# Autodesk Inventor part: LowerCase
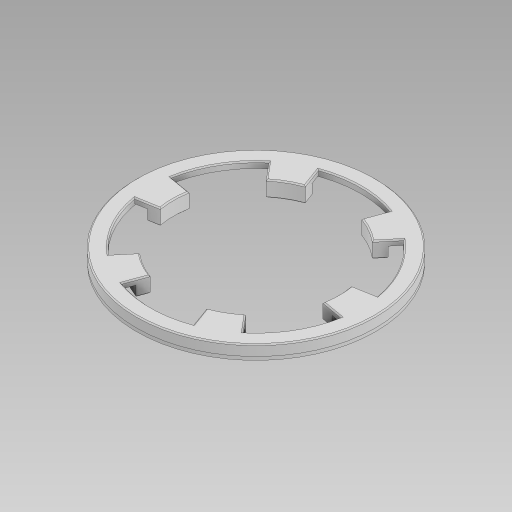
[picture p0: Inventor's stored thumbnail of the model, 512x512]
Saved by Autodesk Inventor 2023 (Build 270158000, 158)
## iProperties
Created: 2024-05
Part Number: LowerCase
Material: 一般
Document SubType Name: Modeling
Designer: kumagai
Density: 1 g/cm^3
Appearance: 既定
Author: kumagai
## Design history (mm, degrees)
derived "CoreSketch.ipt"
  sketch "Vertical"
    geometry: L1 (0, 65.337)-(0, -65.337) reference; L2 (-46.2, 0)-(46.2, 0) reference; L3 (-11, 2)-(11, 2) reference; L4 (11, 2)-(11, -2) reference; L5 (11, -2)-(-11, -2) reference; L6 (-11, -2)-(-11, 2) reference; L7 (11, 2)-(33, 2) reference; L8 (33, 2)-(33, -2) reference; L9 (33, -2)-(11, -2) reference; L10 (11, -2)-(11, 2) reference; L11 (22, 2.772)-(22, -2.683) reference; L12 (-33, 2)-(-11, 2) reference; L13 (-11, 2)-(-11, -2) reference; L14 (-11, -2)-(-33, -2) reference; L15 (-33, -2)-(-33, 2) reference; L16 (-22, 4.087)-(-22, -4.199) reference; L17 (-33, 10)-(-11, 10) reference; L18 (-11, 10)-(-11, 6) reference; L19 (-11, 6)-(-33, 6) reference; L20 (-33, 6)-(-33, 10) reference; L21 (-27.353, 10)-(-16.647, 10) reference; L22 (-16.647, 10)-(-16.647, 16) reference; L23 (-16.647, 16)-(-27.353, 16) reference; L24 (-27.353, 16)-(-27.353, 10) reference; L25 (11, 16)-(33, 16) reference; L26 (33, 16)-(33, 12) reference; L27 (33, 12)-(11, 12) reference; L28 (11, 12)-(11, 16) reference; L29 (16.134, 12)-(27.866, 12) reference; L30 (27.866, 12)-(27.866, 6) reference; L31 (27.866, 6)-(16.134, 6) reference; L32 (16.134, 6)-(16.134, 12) reference; L33 (-22, 18.272)-(-22, 9.031) reference; L34 (22, 22.635)-(22, 12.71) reference; L35 (33, -2)-(35, -2) reference; L36 (35, -2)-(35, 10) reference; L37 (35, 10)-(33, 10) reference; L38 (33, 10)-(33, -2) reference; L39 (0, -4)-(37.5, -4) reference; L40 (40.5, -1)-(40.5, 14) reference; L41 (43.9, -8)-(0, -8) reference; L42 (0, -4)-(0, -8) reference; L43 (35, -2)-(39, -2) reference; L44 (39, -2)-(39, 3.066) reference; L45 (38.45, 8.685)-(41.471, 10.429) reference; L46 (38.45, 10)-(35, 10) reference; L47 (40.5, 9.627)-(41.993, 8.375) reference; L48 (41.55, 3.315)-(40.5, 2.709) reference; L49 (37.5, -4)-(40.5, -1) reference; L50 (-43, 43.294)-(-1, 43.294) reference; L51 (-1, 43.294)-(-1, 26) reference; L52 (-1, 26)-(-43, 26) reference; L53 (-43, 26)-(-43, 43.294) reference; L54 (1, 43.294)-(43, 43.294) reference; L55 (43, 43.294)-(43, 26) reference; L56 (43, 26)-(1, 26) reference; L57 (1, 26)-(1, 43.294) reference; L58 (-22, 45.556)-(-22, 31.232) reference; L59 (22, 47.214)-(22, 32.287) reference; L60 (48, 5.268)-(48, -2.616) reference; L61 (43.6, -11)-(54, -11) reference; L62 (54, -11)-(54, 18) reference; L63 (45.222, -3.461)-(46.5, -2.566) reference; L64 (48, -2.616)-(49.192, -3.808) reference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; A1 r 3.1 centre (40, 6) between (39, 3.066) and (38.45, 8.685) reference; A2 r 3.1 centre (47, -6) between (45.222, -3.461) and (49.192, -3.808) reference; A3 r 3.1 centre (47, 13) between (43.9, 13) and (49, 10.631) reference; 2 further points; 1 other entity
    constraints: 1 other
revolve "回転1" stored, may be unused: angle "d1" = 360 deg
chamfer "面取り1" distance "d2" = 0.5; stored, may be unused: second distance "d3" = 2, angle "d4" = 45 deg
chamfer "面取り2" distance "d5" = 0.1; stored, may be unused: second distance "d6" = 1.5, angle "d7" = 45 deg
sketch "スケッチ4"
  geometry: L1 (38.45, 10)-(35, 10) reference; L2 (40.5, -1)-(40.5, 14) reference; L3 (40.5, 14)-(43.9, 14) reference; L4 (45, 18)-(45, 15.369) reference; L5 (51, 18)-(45, 18) reference; L6 (45, 15.8)-(40.3, 15.8); L7 (40.3, 15.8)-(40.3, 11.2); L8 (40.3, 11.2)-(35.5, 11.2); L9 (35.5, 11.2)-(35.5, 18); L10 (35.5, 18)-(45, 18); L11 (45, 15.369)-(45, 17.5) reference; L12 (45, 15.8)-(45, 17); L13 (45, 17)-(46, 18); L14 (45, 18)-(46, 18); 4 further points
  constraints: 17 end point, 4 horizontal, 2 vertical, 1 point on line
  dimensions: "d8" = 2.2 distance between parallel lines of L6 L10; "d9" = 1 horizontal distance of L12.end L13.end; "d10" = 1 distance from line of L14 L12.end; "d11" = 0.2 distance between parallel lines of L7 L2; "d12" = 1.2 distance between parallel lines of L8 L1; "d13" = 5 distance between parallel lines of L9 L2
revolve "回転2" sketch "スケッチ4" stored, may be unused: angle "d14" = 20 deg
chamfer "面取り3" distance "d18" = 0.5; stored, may be unused: second distance "d19" = 2, angle "d20" = 45 deg
pattern_circular "円形状パターン1" dims angle "d16" = 360 deg
node "ソリッド1"
